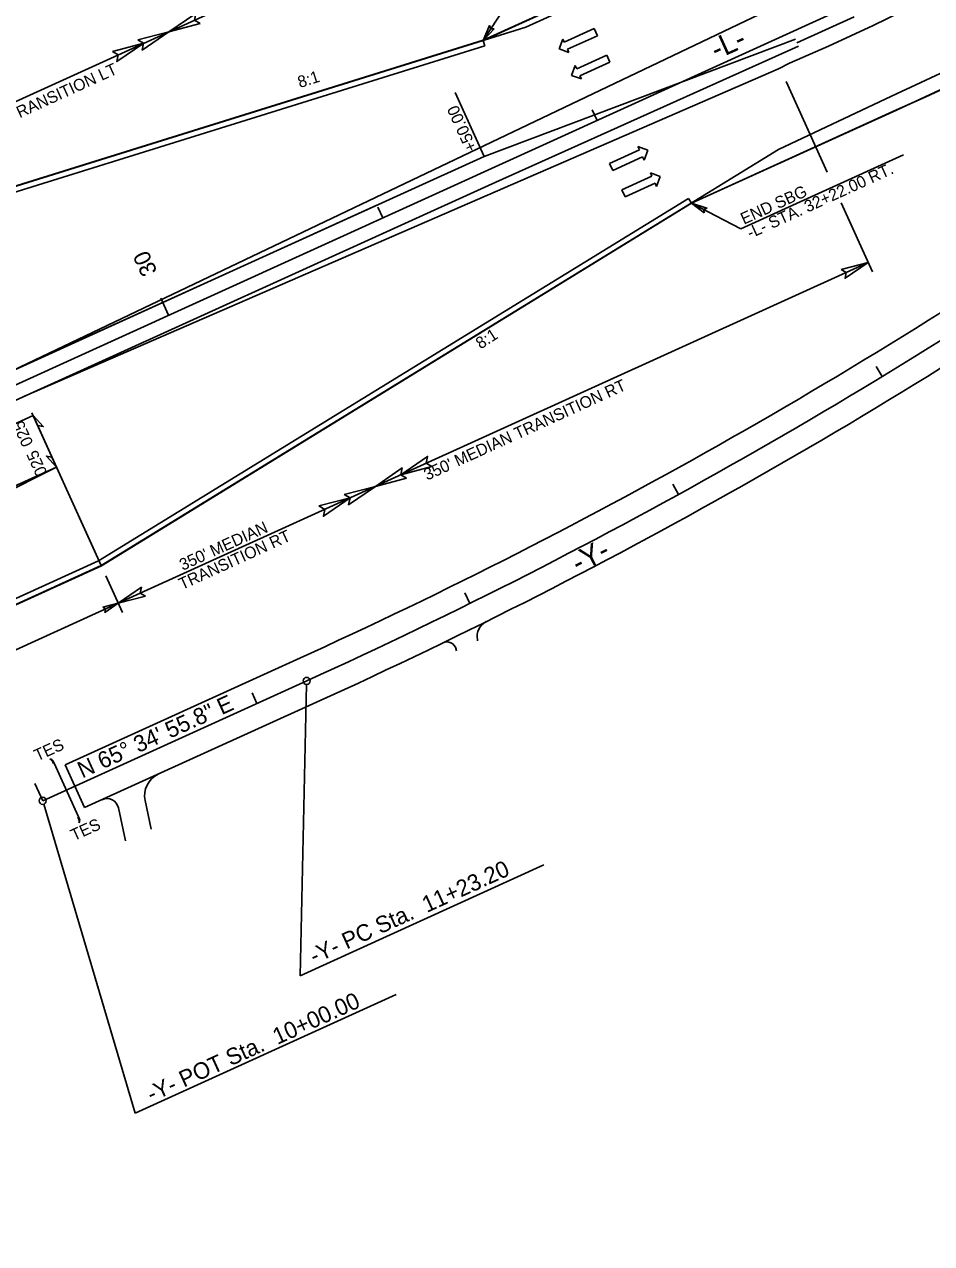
# Model space of a CAD drawing. Extents: x 2242984 to 2250974, y 661492 to 664681.
# Drawn here: x 2249443 to 2249828, y 663221 to 663738 of the extents above; entities that cross this region are included whole.
import ezdxf

# ---------------------------------------------------------------- set-up
doc = ezdxf.new("R2010")
doc.units = 0
for name, color, linetype in [('Prop Conc Shoulder Berm Gutter', 7, 'Continuous'), ('Prop Dimension', 7, 'Continuous'), ('Prop Dimension Text', 7, 'Continuous'), ('Prop DSN Text', 7, 'Continuous'), ('Prop EOT', 7, 'Continuous'), ('Prop EOT Dash', 7, 'Continuous'), ('Prop Guardrail', 7, 'Continuous'), ('Prop Guardrail Anchor Unit CELL', 7, 'Continuous'), ('Prop Guardrail Double Faced', 7, 'Continuous'), ('Prop Horizontal Alignment', 7, 'Continuous'), ('Prop Horizontal Alignment Curve and Spiral Data', 7, 'Continuous'), ('Prop Horizontal Alignment Direction Label', 7, 'Continuous'), ('Prop Horizontal Alignment Station Label', 7, 'Continuous'), ('Prop Horizontal Alignment Tick Label', 7, 'Continuous'), ('Prop Horizontal Alignment Tick Large', 7, 'Continuous'), ('Prop Horizontal Alignment Tick Small', 7, 'Continuous'), ('Prop Lane Arrow CELL', 7, 'Continuous'), ('Prop Lane Lines', 7, 'Continuous'), ('Prop Paved Shoulder', 7, 'Continuous'), ('Prop Superelevation  Arrow CELL', 7, 'Continuous'), ('Prop Superelevation Label', 7, 'Continuous'), ('Prop Terminator CELL', 7, 'Continuous'), ('Scratch_Level_6', 7, 'Continuous'), ('Scratch_Level_8', 7, 'Continuous'), ('Typical Terminator CELL', 7, 'Continuous')]:
    doc.layers.add(name, color=color, linetype=linetype)

# ---------------------------------------------------------------- blocks, each defined once
blk = doc.blocks.new('TERMINATOR')
at = {"layer": 'Typical Terminator CELL'}
blk.add_lwpolyline([(-0.469, 0.081), (0, 0), (-0.471, -0.083), (-0.411, 0)], close=True, dxfattribs=at)

msp = doc.modelspace()

# ---------------------------------------------------------------- linework, layer by layer
at = {"layer": 'Prop Conc Shoulder Berm Gutter'}
for p, q in [((2249638.2, 663729.41), (2249407.42, 663657.51)), ((2249638.2, 663729.41), (2249637.51, 663731.64)), ((2249724.79, 663664.54), (2249474.15, 663510.62)), ((2249724.79, 663664.54), (2249726.01, 663662.56)), ((2249183.08, 663378.4), (2249474.15, 663510.62))]:
    msp.add_line(p, q, dxfattribs=at)
at = {"layer": 'Prop Dimension'}
for p, q in [((2249394.77, 663685.73), (2249854.28, 663894.46)), ((2249766.21, 663714.28), (2249783.71, 663675.76)), ((2249637.91, 663682.4), (2249625.6, 663709.51)), ((2249789.65, 663662.7), (2249802.96, 663633.38)), ((2249482.48, 663492.62), (2249801.15, 663637.38)), ((2249445.73, 663573.54), (2249472.54, 663514.52)), ((2249484.3, 663488.63), (2249477.24, 663504.17)), ((2249482.48, 663492.62), (2249209.34, 663368.55))]:
    msp.add_line(p, q, dxfattribs=at)
at = {"layer": 'Prop DSN Text'}
for p, q in [((2249655.93, 663759.77), (2249637.51, 663731.64)), ((2249816.09, 663683.1), (2249746.99, 663651.61)), ((2249746.99, 663651.61), (2249726.01, 663662.56))]:
    msp.add_line(p, q, dxfattribs=at)
at = {"layer": 'Prop EOT'}
for p, q in [((2248212.61, 663011.89), (2249446.3, 663572.29)), ((2249446.3, 663572.29), (2249456.22, 663550.44)), ((2249188.04, 663415.44), (2249456.22, 663550.44)), ((2249456.22, 663550.44), (2249475.25, 663508.56)), ((2249635.19, 663476.61), (2249635.08, 663477.13)), ((2249625.97, 663473.36), (2249626.22, 663472.39))]:
    msp.add_line(p, q, dxfattribs=at)
at = {"layer": 'Prop EOT Dash'}
for p, q in [((2249459.89, 663423.99), (2249558.41, 663468.72)), ((2249468.15, 663405.78), (2249566.68, 663450.51)), ((2249459.89, 663423.99), (2249468.15, 663405.78)), ((2249496.53, 663396.7), (2249493.87, 663408.75)), ((2249482.54, 663405.67), (2249485.55, 663391.71))]:
    msp.add_line(p, q, dxfattribs=at)
for centre, radius, start, end in [((2248611.75, 665553.89), 2290, 294.41783, 304.80379), ((2248611.75, 665553.89), 2310, 294.41783, 304.80379), ((2249641.95, 663478.51), 7, 116.3994, 191.4085), ((2249622.15, 663472.14), 4, 14.2494, 115.8902), ((2249503.64, 663410.9), 10, 114.4178, 192.4449), ((2249477.66, 663404.6), 5, 12.3126, 114.4178)]:
    msp.add_arc(centre, radius, start, end, dxfattribs=at)
at = {"layer": 'Prop Guardrail'}
for p, q in [((2249771.98, 663792.73), (2249637.51, 663731.64)), ((2249637.51, 663731.64), (2249406.59, 663659.7)), ((2249637.91, 663682.4), (2249770.18, 663732.16)), ((2249771.5, 663729.24), (2249642.88, 663671.47)), ((2249726.01, 663662.56), (2249813.13, 663702.13)), ((2249182.68, 663475.61), (2249637.91, 663682.4)), ((2249642.88, 663671.47), (2249233.17, 663485.36)), ((2249182.68, 663475.61), (2249592.39, 663661.72)), ((2249475.25, 663508.56), (2249726.01, 663662.56)), ((2249167.75, 663368.88), (2249475.25, 663508.56)), ((2249455.21, 663424.61), (2249465.55, 663401.85))]:
    msp.add_line(p, q, dxfattribs=at)
msp.add_arc((2247423.42, 668962.88), 5778.08, 294.430126, 298.67506, dxfattribs=at)
at = {"layer": 'Prop Guardrail Anchor Unit CELL'}
for p, q in [((2249454.95, 663424.5), (2249454.49, 663425.52)), ((2249455.21, 663424.61), (2249454.75, 663425.64)), ((2249455.21, 663424.61), (2249454.95, 663424.5)), ((2249465.55, 663401.85), (2249465.29, 663401.73)), ((2249465.29, 663401.73), (2249465.75, 663400.71)), ((2249465.55, 663401.85), (2249466.01, 663400.82))]:
    msp.add_line(p, q, dxfattribs=at)
for centre, radius, start, end in [((2249453.61, 663425.08), 1.27, 26.0888, 96.4828), ((2249453.07, 663424.79), 1.6, 27.2353, 75.5427), ((2249464.84, 663400.33), 1.27, 312.3529, 22.7469), ((2249464.27, 663400.12), 1.6, 333.2929, 21.6004)]:
    msp.add_arc(centre, radius, start, end, dxfattribs=at)
at = {"layer": 'Prop Guardrail Double Faced'}
msp.add_line((2249770.84, 663730.7), (2249795.14, 663741.74), dxfattribs=at)
at = {"layer": 'Prop Horizontal Alignment'}
for p, q in [((2247500.8, 662705.02), (2249793.08, 663746.29)), ((2249450.36, 663408.68), (2249562.54, 663459.61))]:
    msp.add_line(p, q, dxfattribs=at)
msp.add_arc((2248611.75, 665553.89), 2300, 294.41783, 304.80379, dxfattribs=at)
at = {"layer": 'Prop Horizontal Alignment Station Label'}
for p, q in [((2249562.51, 663458.11), (2249559.76, 663334.35)), ((2249450.79, 663407.24), (2249489.7, 663275.94)), ((2249663.35, 663381.55), (2249559.76, 663334.35)), ((2249600.53, 663326.44), (2249489.7, 663275.94))]:
    msp.add_line(p, q, dxfattribs=at)
for centre in [(2249562.54, 663459.61), (2249562.54, 663459.61), (2249450.36, 663408.68), (2249450.36, 663408.68)]:
    msp.add_circle(centre, 1.5, dxfattribs=at)
at = {"layer": 'Prop Horizontal Alignment Tick Large'}
for p, q in [((2249503.82, 663614.9), (2249500.52, 663622.18)), ((2249450.36, 663408.68), (2249447.06, 663415.97))]:
    msp.add_line(p, q, dxfattribs=at)
at = {"layer": 'Prop Horizontal Alignment Tick Small'}
for p, q in [((2249685.92, 663697.61), (2249683.85, 663702.17)), ((2249594.87, 663656.26), (2249592.8, 663660.81)), ((2249807.1, 663588.91), (2249804.5, 663593.18)), ((2249720.56, 663538.81), (2249718.15, 663543.19)), ((2249631.93, 663492.52), (2249629.71, 663497)), ((2249541.42, 663450.02), (2249539.35, 663454.57))]:
    msp.add_line(p, q, dxfattribs=at)
at = {"layer": 'Prop Lane Arrow CELL'}
for p, q in [((2249671.98, 663730.88), (2249684.72, 663736.69)), ((2249686.09, 663733.68), (2249673.35, 663727.88)), ((2249684.72, 663736.69), (2249686.09, 663733.68)), ((2249669.82, 663728.03), (2249671.36, 663732.25)), ((2249673.97, 663726.51), (2249669.82, 663728.03)), ((2249671.36, 663732.25), (2249671.98, 663730.88)), ((2249673.35, 663727.88), (2249673.97, 663726.51)), ((2249677.27, 663719.65), (2249690.01, 663725.45)), ((2249690.01, 663725.45), (2249691.38, 663722.45)), ((2249675.11, 663716.79), (2249676.65, 663721.01)), ((2249676.65, 663721.01), (2249677.27, 663719.65)), ((2249691.38, 663722.45), (2249678.64, 663716.64)), ((2249679.26, 663715.28), (2249675.11, 663716.79)), ((2249678.64, 663716.64), (2249679.26, 663715.28)), ((2249703.94, 663685.22), (2249703.31, 663686.58)), ((2249703.31, 663686.58), (2249707.47, 663685.07)), ((2249691.2, 663679.41), (2249703.94, 663685.22)), ((2249705.3, 663682.22), (2249692.56, 663676.41)), ((2249705.93, 663680.85), (2249705.3, 663682.22)), ((2249707.47, 663685.07), (2249705.93, 663680.85)), ((2249692.56, 663676.41), (2249691.2, 663679.41)), ((2249696.48, 663668.18), (2249709.22, 663673.98)), ((2249709.22, 663673.98), (2249708.6, 663675.35)), ((2249708.6, 663675.35), (2249712.75, 663673.83)), ((2249712.75, 663673.83), (2249711.22, 663669.62)), ((2249697.85, 663665.18), (2249696.48, 663668.18)), ((2249710.59, 663670.98), (2249697.85, 663665.18)), ((2249711.22, 663669.62), (2249710.59, 663670.98))]:
    msp.add_line(p, q, dxfattribs=at)
at = {"layer": 'Prop Lane Lines'}
msp.add_line((2248759.04, 663233.74), (2249456.25, 663550.45), dxfattribs=at)
at = {"layer": 'Prop Paved Shoulder'}
for p, q in [((2249437.63, 663591.42), (2249853.74, 663789.97)), ((2249655.6, 663737.28), (2249406.59, 663659.7)), ((2249442.6, 663580.5), (2249763, 663719.65)), ((2249763.05, 663685.31), (2249475.25, 663508.56)), ((2249184.04, 663376.28), (2249475.25, 663508.56))]:
    msp.add_line(p, q, dxfattribs=at)
for points in [[(2250163.18, 663918.53), (2250141.76, 663907.17), (2250123.19, 663897.33), (2250103.59, 663886.75), (2250085.93, 663877.2), (2250066.71, 663867.19), (2250050.24, 663858.7), (2250033.81, 663851.08), (2250013.9, 663840.08), (2249997.54, 663832.27), (2249982.72, 663824.86), (2249962.36, 663814.71), (2249947.05, 663807.05), (2249930.38, 663798.85), (2249911.87, 663789.95), (2249894.79, 663781.72), (2249875.22, 663772.32), (2249857.01, 663763.64), (2249837.93, 663754.68), (2249815.49, 663743.88), (2249803.29, 663738.06), (2249784.26, 663729.26), (2249767.73, 663721.96), (2249763, 663719.65)], [(2249763.05, 663685.31), (2249811.06, 663707.92), (2249850.56, 663726.37), (2249885.63, 663742.92), (2249932.97, 663765.08), (2249967.97, 663781.54), (2250003.28, 663798.87), (2250039.45, 663816.82), (2250072.29, 663833.2), (2250110.04, 663851.84), (2250136.3, 663864.69), (2250169.45, 663881.11), (2250179.91, 663886.23)], [(2249843.45, 663822.95), (2249824.73, 663814.35), (2249810.06, 663807.67), (2249787.9, 663797.34), (2249766.72, 663787.83), (2249750.29, 663780.29), (2249732.43, 663772.23), (2249711.61, 663762.73), (2249697.93, 663756.48), (2249655.6, 663737.28)]]:
    msp.add_lwpolyline(points, dxfattribs=at)
at = {"layer": 'Prop Superelevation  Arrow CELL'}
for p in [(2249446.3, 663572.29), (2249456.22, 663550.44)]:
    msp.add_line(p, (2249451.26, 663561.36), dxfattribs=at)
for points in [[(2249446.3, 663572.29), (2249450.6, 663567.65), (2249448.21, 663568.08)], [(2249456.22, 663550.44), (2249451.92, 663555.07), (2249454.31, 663554.65)]]:
    msp.add_lwpolyline(points, close=True, dxfattribs=at)
at = {"layer": 'Prop Terminator CELL'}
for points in [[(2249517.28, 663738.82), (2249504.02, 663735.36), (2249515.39, 663743.16), (2249514.81, 663740.26)], [(2249490.77, 663731.89), (2249504.02, 663735.36), (2249492.66, 663727.56), (2249493.23, 663730.46)], [(2249642.18, 663736.65), (2249637.51, 663731.64), (2249640.23, 663737.98), (2249640.76, 663736.6)], [(2249480.04, 663727.01), (2249493.29, 663730.48), (2249481.93, 663722.68), (2249482.51, 663725.58)], [(2249731.45, 663658.4), (2249726.01, 663662.56), (2249732.58, 663660.48), (2249731.26, 663659.81)], [(2249615.77, 663550.62), (2249602.52, 663547.15), (2249613.89, 663554.95), (2249613.31, 663552.05)], [(2249604.99, 663545.72), (2249591.74, 663542.25), (2249603.11, 663550.05), (2249602.53, 663547.16)], [(2249578.49, 663538.79), (2249591.74, 663542.25), (2249580.37, 663534.46), (2249580.95, 663537.35)], [(2249567.76, 663533.91), (2249581.01, 663537.38), (2249569.65, 663529.58), (2249570.22, 663532.48)], [(2249475.86, 663490.89), (2249482.48, 663492.62), (2249476.8, 663488.72), (2249477.09, 663490.17)]]:
    msp.add_lwpolyline(points, close=True, dxfattribs=at)
at = {"layer": 'Scratch_Level_6'}
for p, q in [((2249637.47, 663731.73), (2249771.94, 663792.82)), ((2249406.56, 663659.79), (2249637.47, 663731.73)), ((2249726.05, 663662.47), (2249813.18, 663702.04)), ((2249475.29, 663508.47), (2249726.05, 663662.47)), ((2249167.72, 663368.76), (2249475.29, 663508.47))]:
    msp.add_line(p, q, dxfattribs=at)
msp.add_arc((2247423.42, 668962.88), 5778.18, 294.430126, 298.67506, dxfattribs=at)
at = {"layer": 'Scratch_Level_8'}
for p, q in [((2249406.56, 663659.78), (2249637.48, 663731.73)), ((2249475.29, 663508.48), (2249726.05, 663662.48)), ((2249172.45, 663370.91), (2249475.29, 663508.48))]:
    msp.add_line(p, q, dxfattribs=at)

# ---------------------------------------------------------------- block references
at = {"layer": 'Prop Dimension', "xscale": 24.999999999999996, "yscale": 25.000000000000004}
for p, rotation in [((2249801.15, 663637.38), 24.430125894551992), ((2249482.48, 663492.62), -155.569874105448)]:
    msp.add_blockref('TERMINATOR', p, dxfattribs=dict(at, rotation=rotation))

# ---------------------------------------------------------------- texts
at = {"layer": 'Prop Dimension'}
msp.add_text('+50.00', height=5, rotation=114.4301, dxfattribs=at).set_placement((2249635.09, 663685.81))
at = {"layer": 'Prop Dimension Text'}
for s, rotation, p in [("505' MEDIAN TRANSITION LT", 24.4979, (2249398.54, 663679.42)), ('8:1', 17.6265, (2249559.64, 663711.41)), ('8:1', 32.7674, (2249636.43, 663600.37)), ("350' MEDIAN TRANSITION RT", 24.4979, (2249613.73, 663544.65)), ("350' MEDIAN", 24.4979, (2249509.85, 663506.35)), ('TRANSITION RT', 24.4979, (2249509.58, 663498.18))]:
    msp.add_text(s, height=5, rotation=rotation, dxfattribs=at).set_placement(p)
at = {"layer": 'Prop DSN Text'}
for s, p in [('-L- STA. 32+22.00 RT.', (2249751.04, 663647.39)), ('END SBG', (2249748.32, 663653.35))]:
    msp.add_text(s, height=5, rotation=24.4979, dxfattribs=at).set_placement(p)
at = {"layer": 'Prop Guardrail Anchor Unit CELL'}
for p in [(2249448.1, 663425.4), (2249463.65, 663391.51)]:
    msp.add_text('TES', height=5, rotation=24.4301, dxfattribs=at).set_placement(p)
at = {"layer": 'Prop Horizontal Alignment Curve and Spiral Data'}
for s, rotation, p in [('-L-', 24.4301, (2249736.65, 663723.33)), ('-Y-', 26.8831, (2249677.89, 663505.16))]:
    msp.add_text(s, height=9, rotation=rotation, dxfattribs=at).set_placement(p)
at = {"layer": 'Prop Horizontal Alignment Direction Label'}
msp.add_text('N 65%%d 34\' 55.8" E', height=7, rotation=24.4178, dxfattribs=at).set_placement((2249467.19, 663418.14))
at = {"layer": 'Prop Horizontal Alignment Station Label'}
for s, p in [('-Y- PC Sta.  11+23.20', (2249565.79, 663339.23)), ('-Y- POT Sta.  10+00.00', (2249496.6, 663280.58))]:
    msp.add_text(s, height=7, rotation=24.4979, dxfattribs=at).set_placement(p)
at = {"layer": 'Prop Horizontal Alignment Tick Label'}
msp.add_text('30', height=7, rotation=114.4301, dxfattribs=at).set_placement((2249499.19, 663633.49))
at = {"layer": 'Prop Superelevation Label'}
for p in [(2249446.51, 663560.51), (2249452.43, 663547.95)]:
    msp.add_text('025', height=5, rotation=114.4979, dxfattribs=at).set_placement(p)

doc.saveas('drawing.dxf')
